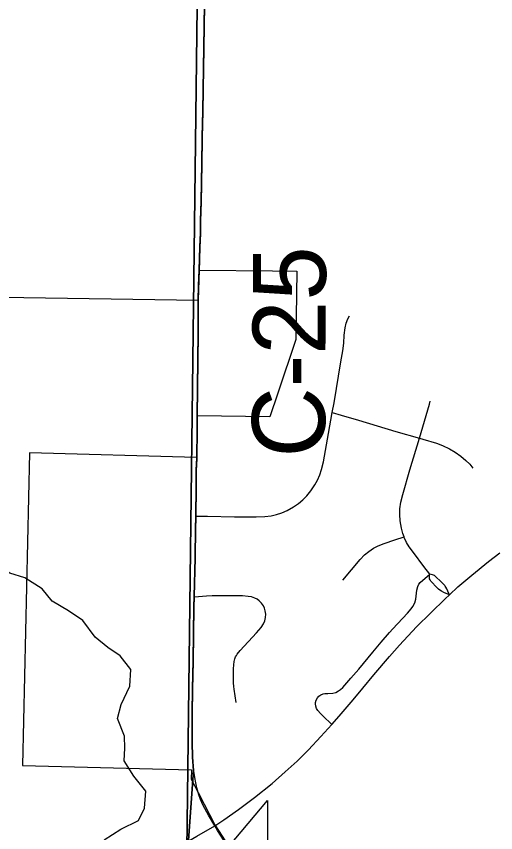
# Model space of a CAD drawing. Extents: x 0 to 34, y 0 to 22.
# Drawn here: x 5.615 to 5.989, y 16.761 to 17.398 of the extents above; entities that cross this region are included whole.
import ezdxf

# ---------------------------------------------------------------- set-up
doc = ezdxf.new("R2010")
doc.units = 0
for name, color, linetype in [('GM_X_City_Street', 7, 'Continuous'), ('GM_X_Corporation', 7, 'Continuous'), ('GM_X_County_Road', 7, 'Continuous'), ('GM_X_County_Road_Text', 7, 'Continuous'), ('GM_X_Minor_River', 7, 'Continuous')]:
    doc.layers.add(name, color=color, linetype=linetype)

msp = doc.modelspace()

# ---------------------------------------------------------------- linework, layer by layer
at = {"layer": 'GM_X_City_Street'}
for points in [[(5.75548, 17.00802), (5.76429, 17.00787), (5.78543, 17.0075), (5.80223, 17.00739), (5.80907, 17.00767), (5.81401, 17.00828), (5.81826, 17.00923), (5.82239, 17.0106), (5.82636, 17.01238), (5.83126, 17.01512), (5.83538, 17.01789), (5.83875, 17.02066), (5.8418, 17.02376), (5.84492, 17.02764), (5.84806, 17.03229), (5.85017, 17.0361), (5.8519, 17.0401), (5.85324, 17.04423), (5.8547, 17.05029), (5.85866, 17.07234), (5.86161, 17.08868), (5.86297, 17.09624), (5.86838, 17.12815), (5.86973, 17.13676), (5.87047, 17.14293), (5.87092, 17.14912), (5.87173, 17.15465), (5.87254, 17.15829), (5.8738, 17.1618), (5.87495, 17.16402)], [(5.93771, 16.96265), (5.93297, 16.96876), (5.92482, 16.97952), (5.92149, 16.9841), (5.91954, 16.98736), (5.91788, 16.99079), (5.91747, 16.99187), (5.91654, 16.99436), (5.9154, 16.99865), (5.9145, 17.00427), (5.91417, 17.00932), (5.91432, 17.01375), (5.91504, 17.01876), (5.91654, 17.02487), (5.9221, 17.04397), (5.92944, 17.06882), (5.93727, 17.09517), (5.93794, 17.09756)], [(5.86161, 17.08868), (5.86841, 17.08672), (5.88211, 17.08276), (5.91123, 17.07408), (5.92944, 17.06882), (5.93208, 17.06806), (5.94275, 17.06481), (5.94737, 17.06301), (5.95295, 17.06032), (5.95724, 17.05781), (5.96181, 17.05462), (5.96562, 17.05144), (5.96867, 17.04837), (5.971, 17.04547)], [(5.86978, 16.95807), (5.88321, 16.97425), (5.88667, 16.97778), (5.89, 16.98054), (5.89363, 16.98289), (5.89746, 16.98489), (5.90204, 16.98676), (5.91026, 16.98948), (5.91747, 16.99187)], [(5.86118, 16.84563), (5.85421, 16.85238), (5.85242, 16.85411), (5.85033, 16.85644), (5.84936, 16.85804), (5.84874, 16.85979), (5.84853, 16.86163), (5.84863, 16.86285), (5.84913, 16.86465), (5.85002, 16.86629), (5.85125, 16.86768), (5.85276, 16.86875), (5.85448, 16.86944), (5.85569, 16.8697), (5.85819, 16.86986), (5.86194, 16.87004), (5.86434, 16.87062), (5.86657, 16.87169), (5.86806, 16.8728), (5.86987, 16.87451), (5.87601, 16.88157), (5.8822, 16.88858), (5.89323, 16.90208), (5.89967, 16.90971), (5.90616, 16.91726), (5.90866, 16.92004), (5.92022, 16.93228), (5.92303, 16.93561), (5.92444, 16.93764), (5.92583, 16.9404), (5.92669, 16.94338), (5.92754, 16.95021), (5.92825, 16.95323), (5.92906, 16.95489), (5.93014, 16.95637), (5.93771, 16.96265)], [(5.95279, 16.94667), (5.94859, 16.9485), (5.94673, 16.94941), (5.94535, 16.95016), (5.94429, 16.95096), (5.94329, 16.95199), (5.93843, 16.95739), (5.93772, 16.95822), (5.93734, 16.95918), (5.93725, 16.96005), (5.93742, 16.9614), (5.93771, 16.96265)], [(5.95279, 16.94667), (5.95229, 16.94779), (5.95071, 16.95142), (5.95002, 16.95271), (5.94959, 16.9534), (5.94916, 16.95397), (5.94753, 16.95563), (5.94586, 16.9573), (5.94264, 16.96044), (5.94117, 16.96165), (5.94051, 16.96201), (5.93972, 16.96232), (5.93864, 16.96258), (5.93771, 16.96265)], [(5.78674, 16.8626), (5.78509, 16.87312), (5.78485, 16.87524), (5.78466, 16.87798), (5.7846, 16.88132), (5.78459, 16.88516), (5.78476, 16.88899), (5.78496, 16.89217), (5.78518, 16.89458), (5.7854, 16.8958), (5.78569, 16.89684), (5.78633, 16.89843), (5.78687, 16.89939), (5.78755, 16.90044), (5.78983, 16.90329), (5.80245, 16.91697), (5.80616, 16.92128), (5.80798, 16.92397), (5.80906, 16.9264), (5.80966, 16.92899), (5.80977, 16.93164), (5.80941, 16.93428), (5.80882, 16.93618), (5.80797, 16.93799), (5.80647, 16.94019), (5.80459, 16.94207), (5.80297, 16.94324), (5.8012, 16.94416), (5.7987, 16.94501), (5.79613, 16.94547), (5.79171, 16.94577), (5.77676, 16.94593), (5.76801, 16.9459), (5.76359, 16.94552), (5.75427, 16.94471)]]:
    msp.add_lwpolyline(points, dxfattribs=at)
at = {"layer": 'GM_X_Corporation'}
for points in [[(4.7439, 17.58074), (5.75807, 17.55374), (5.74588, 16.55703), (4.71407, 16.57495)], [(5.75845, 17.5867), (6.70042, 17.56893), (6.68286, 16.55378), (5.74588, 16.55703), (5.75807, 17.55374)]]:
    msp.add_lwpolyline(points, close=True, dxfattribs=at)
for points in [[(5.74951, 16.7555), (5.75359, 16.80969), (5.75278, 16.82009), (5.75257, 16.83189), (5.75249, 16.85428), (5.75272, 16.87358), (5.75326, 16.89534), (5.75387, 16.93764), (5.75403, 16.94526), (5.75466, 16.97558), (5.75504, 16.99859), (5.75522, 17.00729), (5.75524, 17.00857), (5.75549, 17.03031), (5.75568, 17.04401), (5.75598, 17.05331), (5.75623, 17.07533), (5.7564, 17.08586), (5.75671, 17.10833), (5.75715, 17.15101), (5.75722, 17.1764), (5.7575, 17.18762), (5.75788, 17.19959), (5.75854, 17.21789), (5.75876, 17.22328), (5.75898, 17.22889), (5.75897, 17.23484), (5.75905, 17.24007), (5.75914, 17.24442), (5.75952, 17.25517), (5.75973, 17.26583), (5.75984, 17.27279), (5.75995, 17.27874), (5.76006, 17.28424), (5.76007, 17.28973), (5.76017, 17.29595), (5.76024, 17.30029), (5.76035, 17.30588), (5.76049, 17.31146), (5.7606, 17.31643), (5.76069, 17.32139), (5.76078, 17.32636), (5.76088, 17.33069), (5.76094, 17.33379), (5.76098, 17.33689), (5.76102, 17.34061), (5.7611, 17.34681), (5.76116, 17.35053), (5.76124, 17.35425), (5.76132, 17.35859), (5.7614, 17.36294), (5.76148, 17.3679), (5.76155, 17.37224), (5.76161, 17.37845), (5.76172, 17.38529), (5.76191, 17.39336), (5.76209, 17.40391)], [(5.76209, 17.40391), (5.76191, 17.39336), (5.76172, 17.38529), (5.76161, 17.37845), (5.76155, 17.37224), (5.76148, 17.3679), (5.7614, 17.36294), (5.76132, 17.35859), (5.76124, 17.35425), (5.76116, 17.35053), (5.7611, 17.34681), (5.76102, 17.34061), (5.76098, 17.33689), (5.76094, 17.33379), (5.76088, 17.33069), (5.76078, 17.32636), (5.76069, 17.32139), (5.7606, 17.31643), (5.76049, 17.31146), (5.76035, 17.30588), (5.76024, 17.30029), (5.76017, 17.29595), (5.76007, 17.28973), (5.76006, 17.28424), (5.75995, 17.27874), (5.75984, 17.27279), (5.75973, 17.26583), (5.75952, 17.25517), (5.75914, 17.24442), (5.75905, 17.24007), (5.75897, 17.23484), (5.75898, 17.22889), (5.75876, 17.22328), (5.75854, 17.21789), (5.75788, 17.19959), (5.7575, 17.18762), (5.75722, 17.1764), (5.75715, 17.15101), (5.75671, 17.10833), (5.7564, 17.08586), (5.75623, 17.07533), (5.75598, 17.05331), (5.75568, 17.04401), (5.75549, 17.03031), (5.75524, 17.00857), (5.75522, 17.00729), (5.75504, 16.99859), (5.75466, 16.97558), (5.75403, 16.94526), (5.75387, 16.93764), (5.75326, 16.89534), (5.75272, 16.87358), (5.75249, 16.85428), (5.75257, 16.83189), (5.75278, 16.82009), (5.75359, 16.80969), (5.74951, 16.7555)], [(5.50192, 17.18032), (5.75751, 17.17619), (5.75804, 17.19975), (5.81508, 17.19907), (5.83403, 17.19882), (5.83327, 17.14576), (5.81923, 17.10377), (5.81307, 17.08538), (5.75622, 17.08612), (5.75576, 17.05356), (5.62569, 17.05736), (5.62023, 16.81375), (5.75198, 16.81012), (5.75168, 16.803), (5.75716, 16.79245), (5.76178, 16.78354), (5.77014, 16.76745), (5.78095, 16.75041), (5.81103, 16.78626), (5.81141, 16.70458)]]:
    msp.add_lwpolyline(points, dxfattribs=at)
at = {"layer": 'GM_X_County_Road'}
for points in [[(5.75812, 17.19904), (5.75878, 17.21734), (5.75899, 17.22272), (5.75922, 17.22834), (5.75921, 17.23429), (5.75929, 17.23951), (5.75938, 17.24386), (5.75976, 17.25461), (5.75997, 17.26527), (5.76008, 17.27223), (5.76019, 17.27819), (5.76029, 17.28369), (5.76031, 17.28918), (5.76041, 17.29539), (5.76047, 17.29974), (5.76059, 17.30532), (5.76073, 17.31091), (5.76083, 17.31587), (5.76093, 17.32084), (5.76102, 17.3258), (5.76111, 17.33014), (5.76117, 17.33324), (5.76122, 17.33634), (5.76126, 17.34006), (5.76134, 17.34626), (5.7614, 17.34997), (5.76147, 17.3537), (5.76156, 17.35804), (5.76164, 17.36238), (5.76172, 17.36735), (5.76178, 17.37169), (5.76185, 17.3779), (5.76196, 17.38473), (5.76214, 17.3928), (5.76232, 17.40335)], [(5.75746, 17.17585), (5.75773, 17.18706), (5.75812, 17.19904)], [(5.75664, 17.08531), (5.75695, 17.10778), (5.75739, 17.15045), (5.75746, 17.17585)], [(5.75622, 17.05275), (5.75646, 17.07478), (5.75664, 17.08531)], [(5.75548, 17.00802), (5.75573, 17.02976), (5.75592, 17.04345), (5.75622, 17.05275)], [(5.75427, 16.94471), (5.7549, 16.97503), (5.75528, 16.99804), (5.75546, 17.00674), (5.75548, 17.00802)], [(5.95279, 16.94667), (5.95945, 16.95281), (5.97022, 16.96208), (5.98321, 16.97255), (5.99214, 16.9793)], [(5.75383, 16.80913), (5.75302, 16.81953), (5.75281, 16.83134), (5.75273, 16.85373), (5.75295, 16.87302), (5.7535, 16.89479), (5.75411, 16.93709), (5.75427, 16.94471)], [(5.88529, 16.87381), (5.89407, 16.88434), (5.9062, 16.89847), (5.91394, 16.9074), (5.92726, 16.92172), (5.94945, 16.9436), (5.95279, 16.94667)], [(5.86118, 16.84563), (5.86689, 16.852), (5.87777, 16.86478), (5.88529, 16.87381)], [(5.77003, 16.76661), (5.77699, 16.77123), (5.78864, 16.7794), (5.80112, 16.7887), (5.81468, 16.79962), (5.82498, 16.80864), (5.83412, 16.81709), (5.84298, 16.82584), (5.8528, 16.83624), (5.86118, 16.84563)], [(5.77003, 16.76661), (5.76525, 16.77481), (5.76099, 16.78249), (5.75887, 16.78709), (5.75756, 16.79065), (5.75604, 16.79614), (5.75522, 16.80014), (5.75441, 16.80415), (5.75383, 16.80913)], [(5.74975, 16.75495), (5.75598, 16.75853), (5.77003, 16.76661)], [(5.78093, 16.74943), (5.77682, 16.75556), (5.77217, 16.76293), (5.77003, 16.76661)]]:
    msp.add_lwpolyline(points, dxfattribs=at)
at = {"layer": 'GM_X_Minor_River'}
for points in [[(5.69641, 16.89922), (5.68667, 16.90548), (5.67697, 16.91364), (5.66737, 16.92672), (5.65613, 16.93415), (5.64339, 16.94161), (5.63561, 16.95125), (5.62212, 16.95986), (5.61044, 16.9635), (5.5992, 16.97093), (5.58952, 16.97984), (5.57705, 16.98236), (5.56628, 16.99395), (5.57371, 17.00558), (5.5865, 17.02013), (5.58898, 17.0307), (5.58392, 17.0437), (5.56893, 17.05273), (5.55537, 17.05754), (5.54366, 17.05966), (5.53231, 17.06102), (5.52113, 17.07149), (5.50844, 17.08198)], [(5.68378, 16.75565), (5.69684, 16.76412), (5.71062, 16.77068), (5.71536, 16.78046), (5.71637, 16.79372), (5.70711, 16.80528), (5.69938, 16.8172), (5.69995, 16.82705), (5.69975, 16.83654), (5.69433, 16.85031), (5.6972, 16.86126), (5.70392, 16.87555), (5.70455, 16.88844), (5.69641, 16.89922)]]:
    msp.add_lwpolyline(points, dxfattribs=at)

# ---------------------------------------------------------------- texts
at = {"layer": 'GM_X_County_Road_Text'}
msp.add_text('C-25', height=0.056818, rotation=89.65567, dxfattribs=at).set_placement((5.85578, 17.05349))

doc.saveas('drawing.dxf')
